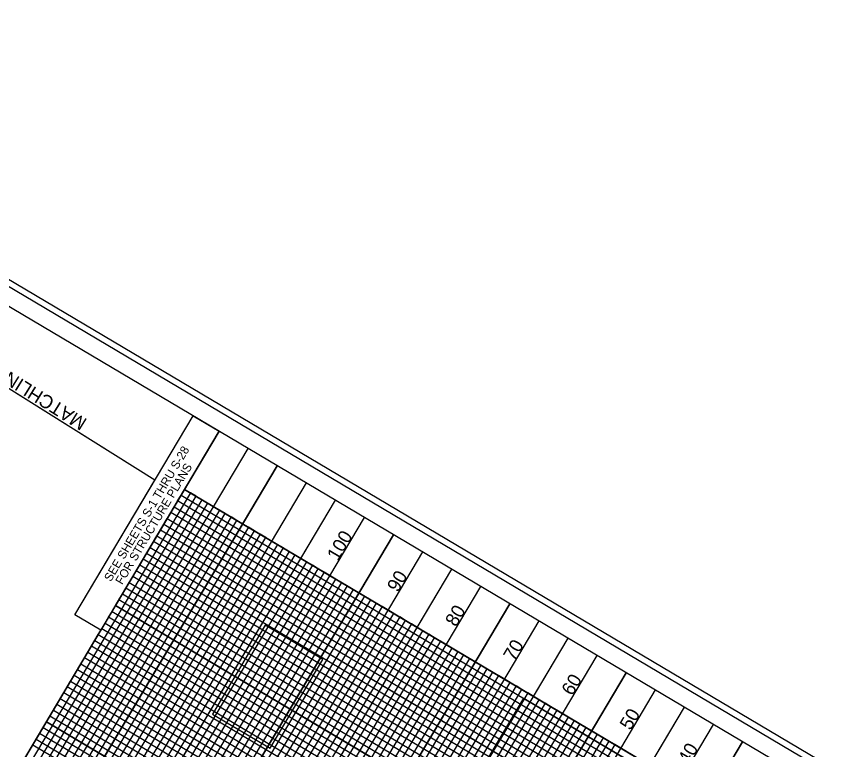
# Model space of a CAD drawing. Extents: x 2137081 to 2142019, y 404041 to 411238.
# Drawn here: x 2141411 to 2142019, y 410499 to 411041 of the extents above; entities that cross this region are included whole.
import ezdxf

# ---------------------------------------------------------------- set-up
doc = ezdxf.new("R2010")
doc.units = 0
for name, color, linetype in [('Exist Vertical Profile Vertical Axis Label', 7, 'Continuous'), ('Prop Dimension', 7, 'Continuous'), ('Prop Dimension Text', 7, 'Continuous'), ('Prop Grid Mask', 7, 'Continuous'), ('Sheet Clip Boundary CELL', 7, 'Continuous'), ('Sheet DOT Grid CELL', 7, 'Continuous'), ('Sheet Layout Profile Border Port 2', 7, 'Continuous'), ('Sheet Plan And Profile CELL', 7, 'Continuous'), ('Sheet Plot Border Inside CELL', 7, 'Continuous'), ('Sheet Plot Border Outside CELL', 7, 'Continuous'), ('Sheet Profile Grid Major CELL', 7, 'Continuous'), ('Sheet Profile Grid Middle CELL', 7, 'Continuous'), ('Sheet Profile Grid Minor CELL', 7, 'Continuous')]:
    doc.layers.add(name, color=color, linetype=linetype)

msp = doc.modelspace()

# ---------------------------------------------------------------- linework, layer by layer
at = {"layer": 'Prop Dimension'}
msp.add_line((2141513.05, 410697.97), (2141213, 410886.12), dxfattribs=at)
msp.add_lwpolyline([(2141453.94, 410598.39), (2141541.35, 410745.65), (2141560.61, 410734.22), (2141473.2, 410586.96)], close=True, dxfattribs=at)
at = {"layer": 'Prop Grid Mask'}
for points in [[(2141598.34, 410499.72), (2141637.31, 410565.38), (2141594.69, 410590.68), (2141555.72, 410525.02)], [(2141936.12, 410447.64), (2141847.6, 410298.5), (2141697.36, 410387.67), (2141785.88, 410536.82)]]:
    msp.add_lwpolyline(points, close=True, dxfattribs=at)
at = {"layer": 'Sheet Clip Boundary CELL'}
msp.add_lwpolyline([(2140795, 409444.32), (2141473.2, 410586.96), (2141453.94, 410598.39), (2141513.05, 410697.97), (2141213, 410886.12), (2141134.78, 410754.33), (2141040.49, 410810.3), (2140938.2, 410637.97), (2140883.25, 410670.58), (2140322.04, 409725.04)], close=True, dxfattribs=at)
at = {"layer": 'Sheet DOT Grid CELL'}
for p, q in [((2140795, 409444.32), (2141560.61, 410734.22)), ((2140838, 409418.8), (2141603.6, 410708.7)), ((2141535.09, 410691.23), (2141943.55, 410448.78)), ((2140880.99, 409393.28), (2141646.6, 410683.18)), ((2140923.99, 409367.76), (2141689.6, 410657.66)), ((2141509.57, 410648.23), (2141918.03, 410405.79)), ((2140966.99, 409342.24), (2141732.59, 410632.14)), ((2141009.98, 409316.72), (2141775.59, 410606.62)), ((2141484.04, 410605.23), (2141892.51, 410362.79)), ((2141052.98, 409291.2), (2141818.59, 410581.1)), ((2141458.52, 410562.24), (2141866.99, 410319.79)), ((2141095.98, 409265.68), (2141861.58, 410555.58)), ((2141138.97, 409240.16), (2141904.58, 410530.06)), ((2141433, 410519.24), (2141841.47, 410276.8)), ((2141181.97, 409214.64), (2141947.58, 410504.54))]:
    msp.add_line(p, q, dxfattribs=at)
at = {"layer": 'Sheet Layout Profile Border Port 2'}
msp.add_lwpolyline([(2140820.52, 409487.32), (2141535.09, 410691.23), (2141943.55, 410448.78), (2141228.99, 409244.88)], close=True, dxfattribs=at)
at = {"layer": 'Sheet Plan And Profile CELL'}
msp.add_lwpolyline([(2141087.64, 411014.95), (2140322.04, 409725.04), (2141224.97, 409189.12), (2141990.57, 410479.02)], close=True, dxfattribs=at)
at = {"layer": 'Sheet Plot Border Inside CELL'}
msp.add_lwpolyline([(2141148.77, 409055.84), (2141999.1, 410488.49), (2141091.87, 411026.97), (2140241.54, 409594.32)], close=True, dxfattribs=at)
at = {"layer": 'Sheet Plot Border Outside CELL'}
msp.add_lwpolyline([(2141159.33, 409034.46), (2142018.6, 410482.16), (2141076.97, 411041.05), (2140217.7, 409593.35)], close=True, dxfattribs=at)
at = {"layer": 'Sheet Profile Grid Major CELL'}
for points in [[(2140795, 409444.32), (2141560.61, 410734.22)], [(2141603.6, 410708.7), (2140838, 409418.8), (2140880.99, 409393.28), (2141646.6, 410683.18)], [(2141943.55, 410448.78), (2141535.09, 410691.23)], [(2141689.6, 410657.66), (2140923.99, 409367.76), (2140966.99, 409342.24), (2141732.59, 410632.14)], [(2141892.51, 410362.79), (2141484.04, 410605.23), (2141509.57, 410648.23), (2141918.03, 410405.79)], [(2141775.59, 410606.62), (2141009.98, 409316.72), (2141052.98, 409291.2), (2141818.59, 410581.1)], [(2141841.47, 410276.8), (2141433, 410519.24), (2141458.52, 410562.24), (2141866.99, 410319.79)], [(2141861.58, 410555.58), (2141095.98, 409265.68), (2141138.97, 409240.16), (2141904.58, 410530.06)], [(2141947.58, 410504.54), (2141181.97, 409214.64)]]:
    msp.add_lwpolyline(points, dxfattribs=at)
at = {"layer": 'Sheet Profile Grid Middle CELL'}
for p, q in [((2140816.5, 409431.56), (2141582.1, 410721.46)), ((2141625.1, 410695.94), (2140859.49, 409406.04)), ((2140902.49, 409380.52), (2141668.1, 410670.42)), ((2141711.09, 410644.9), (2140945.49, 409355)), ((2140988.48, 409329.48), (2141754.09, 410619.38)), ((2141797.09, 410593.86), (2141031.48, 409303.96)), ((2141074.48, 409278.44), (2141840.08, 410568.34)), ((2141883.08, 410542.82), (2141117.48, 409252.92)), ((2141160.47, 409227.4), (2141926.08, 410517.3))]:
    msp.add_line(p, q, dxfattribs=at)
for points in [[(2141905.27, 410384.29), (2141496.81, 410626.73), (2141522.33, 410669.73), (2141930.79, 410427.29)], [(2141854.23, 410298.3), (2141445.76, 410540.74), (2141471.28, 410583.73), (2141879.75, 410341.29)]]:
    msp.add_lwpolyline(points, dxfattribs=at)
at = {"layer": 'Sheet Profile Grid Minor CELL'}
for points in [[(2140829.12, 409482.21), (2141543.68, 410686.12), (2141539.38, 410688.67), (2140824.82, 409484.77)], [(2140837.72, 409477.11), (2141552.28, 410681.02), (2141547.98, 410683.57), (2140833.42, 409479.66)], [(2141938.45, 410440.19), (2141529.98, 410682.63), (2141532.53, 410686.93), (2141941, 410444.48)], [(2140850.62, 409469.45), (2141565.18, 410673.36), (2141560.88, 410675.91), (2140846.32, 409472.01)], [(2141933.35, 410431.59), (2141524.88, 410674.03), (2141527.43, 410678.33), (2141935.9, 410435.89)], [(2140859.22, 409464.35), (2141573.78, 410668.26), (2141569.48, 410670.81), (2140854.92, 409466.9)], [(2140872.12, 409456.69), (2141586.68, 410660.6), (2141582.38, 410663.15), (2140867.82, 409459.25)], [(2141925.69, 410418.69), (2141517.22, 410661.13), (2141519.77, 410665.43), (2141928.24, 410422.99)], [(2140880.72, 409451.59), (2141595.28, 410655.5), (2141590.98, 410658.05), (2140876.42, 409454.14)], [(2141920.59, 410410.09), (2141512.12, 410652.53), (2141514.67, 410656.83), (2141923.14, 410414.39)], [(2140893.61, 409443.93), (2141608.18, 410647.84), (2141603.88, 410650.39), (2140889.31, 409446.49)], [(2140902.21, 409438.83), (2141616.78, 410642.74), (2141612.48, 410645.29), (2140897.91, 409441.38)], [(2141912.93, 410397.19), (2141504.46, 410639.63), (2141507.01, 410643.93), (2141915.48, 410401.49)], [(2140910.81, 409433.73), (2141625.38, 410637.63)], [(2140919.41, 409428.62), (2141633.98, 410632.53), (2141629.68, 410635.08), (2140915.11, 409431.17)], [(2141907.83, 410388.59), (2141499.36, 410631.03), (2141501.91, 410635.33), (2141910.38, 410392.89)], [(2140932.31, 409420.97), (2141646.88, 410624.87), (2141638.28, 410629.98), (2140923.71, 409426.07)], [(2140940.91, 409415.86), (2141655.48, 410619.77), (2141651.18, 410622.32), (2140936.61, 409418.41)], [(2141900.17, 410375.69), (2141491.7, 410618.13), (2141494.25, 410622.43), (2141902.72, 410379.99)], [(2140953.81, 409408.21), (2141668.38, 410612.11), (2141659.78, 410617.22), (2140945.21, 409413.31)], [(2140962.41, 409403.1), (2141676.97, 410607.01), (2141672.67, 410609.56), (2140958.11, 409405.65)], [(2141895.07, 410367.09), (2141486.6, 410609.53), (2141489.15, 410613.83), (2141897.62, 410371.39)], [(2140975.31, 409395.45), (2141689.87, 410599.35), (2141681.27, 410604.46), (2140966.71, 409400.55)], [(2140983.91, 409390.34), (2141698.47, 410594.25), (2141694.17, 410596.8), (2140979.61, 409392.89)], [(2141887.41, 410354.19), (2141478.94, 410596.63), (2141481.49, 410600.93), (2141889.96, 410358.49)], [(2140996.81, 409382.69), (2141711.37, 410586.59), (2141702.77, 410591.7), (2140988.21, 409387.79)], [(2141882.31, 410345.59), (2141473.84, 410588.03), (2141476.39, 410592.33), (2141884.86, 410349.89)], [(2141005.41, 409377.58), (2141719.97, 410581.49), (2141715.67, 410584.04), (2141001.11, 409380.13)], [(2141018.3, 409369.92), (2141732.87, 410573.83), (2141724.27, 410578.94), (2141009.71, 409375.03)], [(2141874.65, 410332.69), (2141466.18, 410575.14), (2141468.73, 410579.44), (2141877.2, 410336.99)], [(2141026.9, 409364.82), (2141741.47, 410568.73), (2141737.17, 410571.28), (2141022.6, 409367.37)], [(2141039.8, 409357.16), (2141754.37, 410561.07), (2141745.77, 410566.18), (2141031.2, 409362.27)], [(2141869.55, 410324.09), (2141461.08, 410566.54), (2141463.63, 410570.84), (2141872.1, 410328.39)], [(2141048.4, 409352.06), (2141762.97, 410555.97), (2141758.67, 410558.52), (2141044.1, 409354.61)], [(2141861.89, 410311.2), (2141453.42, 410553.64), (2141455.97, 410557.94), (2141864.44, 410315.49)], [(2141061.3, 409344.4), (2141775.87, 410548.31), (2141767.27, 410553.42), (2141052.7, 409349.51)], [(2141856.79, 410302.6), (2141448.32, 410545.04), (2141450.87, 410549.34), (2141859.34, 410306.9)], [(2141069.9, 409339.3), (2141784.47, 410543.21), (2141780.17, 410545.76), (2141065.6, 409341.85)], [(2141082.8, 409331.64), (2141797.37, 410535.55), (2141788.77, 410540.66), (2141074.2, 409336.75)], [(2141849.13, 410289.7), (2141440.66, 410532.14), (2141443.21, 410536.44), (2141851.68, 410294)], [(2141091.4, 409326.54), (2141805.96, 410530.45), (2141801.67, 410533), (2141087.1, 409329.09)], [(2141104.3, 409318.88), (2141818.86, 410522.79), (2141810.26, 410527.9), (2141095.7, 409323.99)], [(2141844.03, 410281.1), (2141435.56, 410523.54), (2141438.11, 410527.84), (2141846.58, 410285.4)], [(2141112.9, 409313.78), (2141827.46, 410517.69), (2141823.16, 410520.24), (2141108.6, 409316.33)], [(2141125.8, 409306.12), (2141840.36, 410510.03), (2141831.76, 410515.14), (2141117.2, 409311.23)], [(2141836.37, 410268.2), (2141427.9, 410510.64), (2141430.45, 410514.94), (2141838.92, 410272.5)], [(2141134.4, 409301.02), (2141848.96, 410504.93), (2141844.66, 410507.48), (2141130.1, 409303.57)], [(2141831.27, 410259.6), (2141422.8, 410502.04), (2141425.35, 410506.34), (2141833.82, 410263.9)], [(2141861.86, 410497.27), (2141853.26, 410502.38), (2141138.7, 409298.47)]]:
    msp.add_lwpolyline(points, dxfattribs=at)

# ---------------------------------------------------------------- texts
at = {"layer": 'Exist Vertical Profile Vertical Axis Label'}
for s, p in [('100', (2141648.35, 410637.64)), ('90', (2141692.75, 410614.49)), ('80', (2141735.75, 410588.97)), ('70', (2141778.74, 410563.45)), ('60', (2141821.74, 410537.93)), ('50', (2141864.74, 410512.41)), ('40', (2141907.73, 410486.89))]:
    msp.add_text(s, height=10, rotation=59.30926, dxfattribs=at).set_placement(p)
at = {"layer": 'Prop Dimension'}
for s, p in [('SEE SHEETS S-1 THRU S-28', (2141480.61, 410622.49)), (' FOR STRUCTURE PLANS', (2141487.71, 410618.28))]:
    msp.add_text(s, height=6.3, rotation=59.30926, dxfattribs=at).set_placement(p)
at = {"layer": 'Prop Dimension Text'}
msp.add_text('MATCHLINE SHEET 5 -LREV- STA. 27+00.00', height=10, rotation=148.02363, dxfattribs=at).set_placement((2141463.7, 410742.75))

doc.saveas('drawing.dxf')
